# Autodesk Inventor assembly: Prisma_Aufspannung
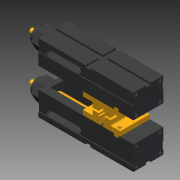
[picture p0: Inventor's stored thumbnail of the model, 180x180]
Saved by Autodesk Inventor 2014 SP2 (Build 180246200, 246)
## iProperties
Created: 2015-06
Part Number: Prisma_Aufspannung
Document SubType Name: Assembly
Designer: e_krauts
Mass: 8690.96 g
Surface Area: 10177 cm^2
Volume: 8690.96 cm^3
Density: 1 g/cm^3
Author: e_krauts
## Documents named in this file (4)
- C:\Users\e_krauts\AppData\Local\SolidCAM Temporary Files\PRISMA_AUFSPANNUNG-3\DesignModel.iam
- Z:\VDW-Nachwuchsstiftung Intern\Mitarbeiter Ablage\Steffen Krauth\IVCAM\Prisma mit Passfedernut.ipt
- C:\Users\e_krauts\AppData\Local\SolidCAM Temporary Files\PRISMA_AUFSPANNUNG-3\Schraubstock.iam
- C:\Users\e_krauts\AppData\Local\SolidCAM Temporary Files\PRISMA_AUFSPANNUNG-3\Prisma mit Passfedernut-01.ipt
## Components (3 placed, 2 different names)
1. Prisma mit Passfedernut-01:1 — Passend:1, Passend:2, Fluchtend:1, Passend:3, Passend:4, Passend:5, Fluchtend:2, Passend:6
2. Schraubstock:1 [sub-assembly] — Passend:1, Passend:2, Fluchtend:1, Passend:3
3. Schraubstock:2 [sub-assembly] — Passend:4, Passend:5, Fluchtend:2, Passend:6
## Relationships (8: Mate 6, Flush 2)
- Passend:1 [Mate]: Prisma mit Passfedernut-01:1 ↔ Schraubstock:1
- Passend:2 [Mate]: Prisma mit Passfedernut-01:1 ↔ Schraubstock:1
- Fluchtend:1 [Flush]: Prisma mit Passfedernut-01:1 ↔ Schraubstock:1
- Passend:3 [Mate]: Prisma mit Passfedernut-01:1 ↔ Schraubstock:1
- Passend:4 [Mate]: Prisma mit Passfedernut-01:1 ↔ Schraubstock:2
- Passend:5 [Mate]: Prisma mit Passfedernut-01:1 ↔ Schraubstock:2
- Fluchtend:2 [Flush]: Prisma mit Passfedernut-01:1 ↔ Schraubstock:2
- Passend:6 [Mate]: Prisma mit Passfedernut-01:1 ↔ Schraubstock:2
